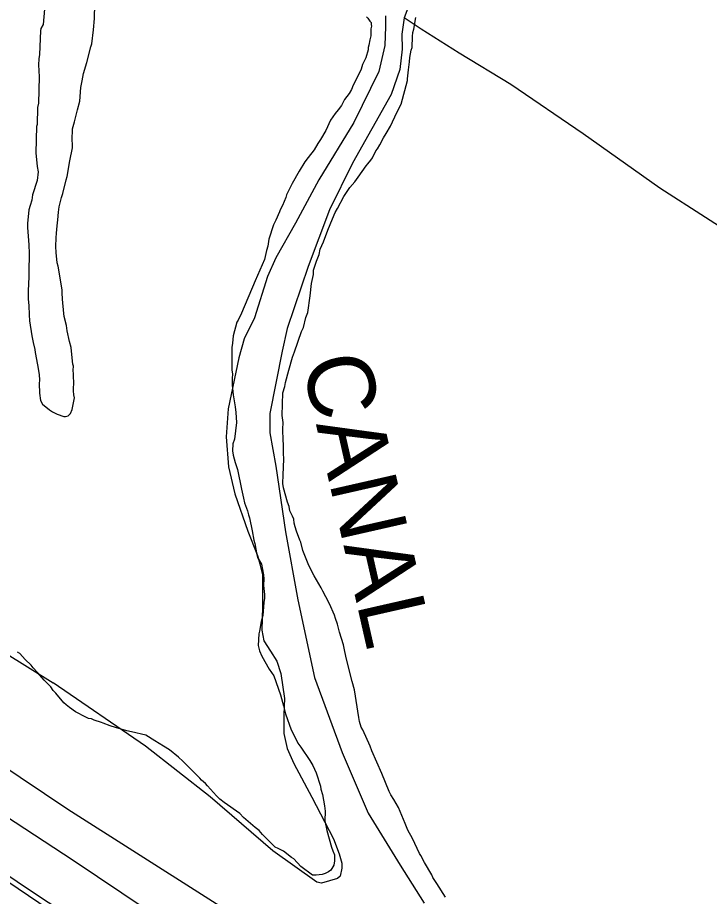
# Model space of a CAD drawing. Extents: x 3715084 to 3753216, y 488173 to 513963.
# Drawn here: x 3720247 to 3721106, y 496938 to 498029 of the extents above; entities that cross this region are included whole.
import ezdxf

# ---------------------------------------------------------------- set-up
doc = ezdxf.new("R2010")
doc.units = 0
for name, color, linetype in [('V-LEVE-TOET', 7, 'Continuous'), ('V-RIVR-IDEN', 7, 'Continuous'), ('V-SITE-VEGE', 7, 'Continuous'), ('V-TOPO-SHOR', 7, 'Continuous'), ('V-WETL-SWMP', 7, 'Continuous')]:
    doc.layers.add(name, color=color, linetype=linetype)

msp = doc.modelspace()

# ---------------------------------------------------------------- linework, layer by layer
at = {"layer": 'V-LEVE-TOET'}
for points in [[(3719301.4, 497645.3), (3719334, 497624.6), (3719454.3, 497539.9), (3719643.7, 497419.4), (3719836.8, 497295), (3719988.8, 497197.6), (3720147.5, 497093.2), (3720315.9, 496983.2)], [(3720181.6, 496999.6), (3720279.1, 496934.7), (3720444.1, 496828.8), (3720616.4, 496722.2)], [(3720315.9, 496983.2), (3720496, 496862.2), (3720657.3, 496764.2)]]:
    msp.add_lwpolyline(points, dxfattribs=at)
at = {"layer": 'V-SITE-VEGE'}
for p, q in [((3720283.9, 498079.1), (3720278.7, 498020.3)), ((3720342.4, 498027.6), (3720342.9, 498045.5)), ((3720341, 498013.5), (3720342.4, 498027.6)), ((3720680.1, 498029.8), (3720681.7, 498028.1)), ((3720681.7, 498028.1), (3720684.3, 498024.3)), ((3720739, 498014.5), (3720741.6, 498029.1)), ((3720275.8, 498015.1), (3720275.2, 498012.4)), ((3720278.7, 498020.3), (3720275.8, 498015.1)), ((3720684.3, 498024.3), (3720685.9, 498022.6)), ((3720685.7, 498015), (3720685.5, 498006.3)), ((3720686.3, 498018.2), (3720685.7, 498015)), ((3720685.9, 498022.6), (3720685.9, 498020.4)), ((3720685.9, 498020.4), (3720686.3, 498018.2)), ((3720275.2, 498012.4), (3720274.7, 497992.9)), ((3720338.9, 497996.1), (3720341, 498013.5)), ((3720685.5, 498006.3), (3720684.3, 498001.4)), ((3720736.8, 497991.7), (3720737.2, 498005.3)), ((3720737.2, 498005.3), (3720737.8, 498010.2)), ((3720737.8, 498010.2), (3720739, 498014.5)), ((3720337.7, 497992.4), (3720338.9, 497996.1)), ((3720683, 497994.4), (3720682.4, 497991.7)), ((3720684.3, 498001.4), (3720683, 497994.4)), ((3720273.9, 497982.6), (3720273.8, 497980.4)), ((3720274.7, 497992.9), (3720273.9, 497982.6)), ((3720332.9, 497972.9), (3720337.7, 497992.4)), ((3720682.3, 497989), (3720679.4, 497978.7)), ((3720682.4, 497991.7), (3720682.3, 497989)), ((3720733.8, 497979.3), (3720735.7, 497988.5)), ((3720735.7, 497988.5), (3720736.8, 497991.7)), ((3720273.2, 497977.7), (3720273, 497970.1)), ((3720273.8, 497980.4), (3720273.2, 497977.7)), ((3720328.7, 497959.4), (3720332.9, 497972.9)), ((3720679.4, 497978.7), (3720675.3, 497970.7)), ((3720732.3, 497964.1), (3720733.7, 497973.9)), ((3720733.7, 497973.9), (3720733.8, 497979.3)), ((3720273, 497970.1), (3720273.7, 497955.4)), ((3720672.4, 497962.1), (3720663.8, 497944.9)), ((3720673.6, 497964.7), (3720672.4, 497962.1)), ((3720675.3, 497970.7), (3720673.6, 497964.7)), ((3720730.9, 497952.7), (3720732.3, 497964.1)), ((3720273.7, 497955.4), (3720272.9, 497922.8)), ((3720325.6, 497942.1), (3720326.9, 497950.2)), ((3720326.9, 497950.2), (3720328.7, 497959.4)), ((3720723.1, 497921.4), (3720730.9, 497950.6)), ((3720730.9, 497950.6), (3720730.9, 497952.7)), ((3720324.1, 497925.3), (3720325.6, 497942.1)), ((3720661.5, 497939.5), (3720658.7, 497934.7)), ((3720663.8, 497944.9), (3720661.5, 497939.5)), ((3720658.7, 497934.7), (3720653, 497927.2)), ((3720271.7, 497917.4), (3720271.1, 497896.2)), ((3720272.9, 497922.8), (3720271.7, 497917.4)), ((3720321.1, 497914.5), (3720324.1, 497925.3)), ((3720649, 497919.7), (3720645.1, 497914.4)), ((3720653, 497927.2), (3720649, 497919.7)), ((3720717.9, 497911.2), (3720723.1, 497921.4)), ((3720317.4, 497899.4), (3720321.1, 497914.5)), ((3720638.4, 497905.8), (3720635.5, 497901.6)), ((3720641.2, 497909.6), (3720638.4, 497905.8)), ((3720645.1, 497914.4), (3720641.2, 497909.6)), ((3720709.9, 497894), (3720717.9, 497911.2)), ((3720271.1, 497896.2), (3720270.5, 497893.5)), ((3720315, 497890.7), (3720317.4, 497899.4)), ((3720635.5, 497901.6), (3720629.8, 497888.7)), ((3720270.5, 497893.5), (3720269.7, 497860.9)), ((3720314.7, 497876.6), (3720315, 497890.7)), ((3720629.8, 497888.7), (3720622.9, 497877.4)), ((3720701.3, 497879.5), (3720704.7, 497884.9)), ((3720704.7, 497884.9), (3720709.9, 497894)), ((3720315.1, 497871.7), (3720314.7, 497876.6)), ((3720622.9, 497877.4), (3720619.6, 497872.6)), ((3720696.8, 497871), (3720701.3, 497879.5)), ((3720311.8, 497851.1), (3720315, 497867.3)), ((3720315, 497867.3), (3720315.1, 497871.7)), ((3720615, 497864.6), (3720607.7, 497855)), ((3720619.6, 497872.6), (3720615, 497864.6)), ((3720687.7, 497854.9), (3720691.7, 497863.5)), ((3720691.7, 497863.5), (3720693.9, 497866.1)), ((3720693.9, 497866.1), (3720696.8, 497871)), ((3720269.7, 497860.9), (3720271.4, 497844)), ((3720308.6, 497831.6), (3720311.8, 497851.1)), ((3720607.7, 497855), (3720603.8, 497849.6)), ((3720682, 497847.4), (3720685.4, 497851.7)), ((3720685.4, 497851.7), (3720687.7, 497854.9)), ((3720271.4, 497844), (3720272.3, 497837.4)), ((3720603.8, 497849.6), (3720596.4, 497838.4)), ((3720669.7, 497830.9), (3720679.8, 497844.8)), ((3720679.8, 497844.8), (3720682, 497847.4)), ((3720272.3, 497837.4), (3720271, 497826.6)), ((3720307.4, 497827.3), (3720308.6, 497831.6)), ((3720596.4, 497838.4), (3720587.8, 497822.9)), ((3720665.7, 497825), (3720669.7, 497830.9)), ((3720271, 497826.6), (3720265.6, 497808.8)), ((3720303.2, 497810.6), (3720307.4, 497827.3)), ((3720587.8, 497822.9), (3720581, 497808.9)), ((3720659.5, 497818.1), (3720665.7, 497825)), ((3720265.6, 497808.8), (3720264.4, 497802.3)), ((3720301.4, 497805.7), (3720303.2, 497810.6)), ((3720581, 497808.9), (3720579.8, 497805.7)), ((3720652.2, 497806.9), (3720659.5, 497818.1)), ((3720264.4, 497802.3), (3720262.6, 497795.8)), ((3720298.4, 497793.8), (3720301.4, 497805.7)), ((3720579.8, 497805.7), (3720575.7, 497795.4)), ((3720644.2, 497791.8), (3720652.2, 497806.9)), ((3720260.8, 497790.4), (3720259.3, 497773.1)), ((3720262.6, 497795.8), (3720260.8, 497790.4)), ((3720296.9, 497777.6), (3720297.7, 497787.3)), ((3720297.7, 497787.3), (3720298.4, 497793.8)), ((3720572.3, 497787.9), (3720567.6, 497777.2)), ((3720572.9, 497790.1), (3720572.3, 497787.9)), ((3720575.7, 497795.4), (3720572.9, 497790.1)), ((3720637.9, 497779), (3720641.4, 497787)), ((3720641.4, 497787), (3720644.2, 497791.8)), ((3720296.2, 497770.5), (3720296.9, 497777.6)), ((3720567.6, 497777.2), (3720564.8, 497771.8)), ((3720632.1, 497765), (3720637.9, 497779)), ((3720259.3, 497773.1), (3720259.2, 497768.2)), ((3720259.2, 497768.2), (3720260.8, 497746.9)), ((3720295.4, 497761.3), (3720296.2, 497770.5)), ((3720564.8, 497771.8), (3720558.9, 497754)), ((3720626.8, 497750.4), (3720632.1, 497765)), ((3720294.4, 497744.5), (3720294.7, 497755.3)), ((3720294.7, 497755.3), (3720295.4, 497761.3)), ((3720558.9, 497754), (3720557.6, 497745.3)), ((3720260.8, 497746.9), (3720261.1, 497736.1)), ((3720294.8, 497737.4), (3720294.4, 497744.5)), ((3720557.6, 497745.3), (3720555.8, 497739.9)), ((3720622.8, 497741.3), (3720626.8, 497750.4)), ((3720261.1, 497736.1), (3720261, 497713.2)), ((3720296.1, 497724.3), (3720294.8, 497737.4)), ((3720555.8, 497739.9), (3720553.4, 497728.6)), ((3720618.1, 497726.7), (3720621.5, 497734.8)), ((3720621.5, 497734.8), (3720622.8, 497741.3)), ((3720297.1, 497720.5), (3720296.1, 497724.3)), ((3720302.3, 497691), (3720297.1, 497720.5)), ((3720553.4, 497728.6), (3720541.8, 497702.2)), ((3720614.5, 497715.4), (3720618.1, 497726.7)), ((3720261, 497713.2), (3720260.9, 497707.3)), ((3720611.9, 497698.6), (3720614.4, 497710)), ((3720614.4, 497710), (3720614.5, 497715.4)), ((3720260.9, 497707.3), (3720260.6, 497698)), ((3720541.8, 497702.2), (3720525, 497661.9)), ((3720610.4, 497683.4), (3720611.9, 497698.6)), ((3720260.6, 497698), (3720259.9, 497689.9)), ((3720259.9, 497689.9), (3720260.2, 497679.5)), ((3720302.2, 497687.2), (3720302.3, 497691)), ((3720260.2, 497679.5), (3720261, 497671.4)), ((3720302.6, 497679.5), (3720302.2, 497687.2)), ((3720304.3, 497661.6), (3720302.6, 497679.5)), ((3720607.2, 497662.8), (3720610.4, 497683.4)), ((3720261, 497671.4), (3720261.3, 497659.9)), ((3720261.3, 497659.9), (3720261.6, 497652.3)), ((3720304.7, 497657.7), (3720304.3, 497661.6)), ((3720307.7, 497646.8), (3720304.7, 497657.7)), ((3720525, 497661.9), (3720521, 497653.3)), ((3720601.8, 497644), (3720604.9, 497656.4)), ((3720604.9, 497656.4), (3720607.2, 497662.8)), ((3720261.6, 497652.3), (3720264.4, 497633.8)), ((3720308.6, 497640.2), (3720307.7, 497646.8)), ((3720519.3, 497650.6), (3720514.5, 497633.9)), ((3720521, 497653.3), (3720519.3, 497650.6)), ((3720599.5, 497639.1), (3720601.8, 497644)), ((3720264.4, 497633.8), (3720266.4, 497625.6)), ((3720311.5, 497626.6), (3720308.6, 497640.2)), ((3720514.5, 497633.9), (3720513.7, 497624.7)), ((3720590.7, 497613.8), (3720599.5, 497639.1)), ((3720266.4, 497625.6), (3720268.3, 497616.8)), ((3720313.5, 497619.5), (3720311.5, 497626.6)), ((3720513.7, 497624.7), (3720513.1, 497619.3)), ((3720268.3, 497616.8), (3720268.8, 497613)), ((3720268.8, 497613), (3720271.6, 497597.7)), ((3720313.9, 497614.6), (3720313.5, 497619.5)), ((3720315.7, 497598.7), (3720313.9, 497614.6)), ((3720513, 497616), (3720512.9, 497591.5)), ((3720513.1, 497619.3), (3720513, 497616)), ((3720588.4, 497607.3), (3720590.7, 497613.8)), ((3720583.6, 497591.1), (3720588.4, 497607.3)), ((3720271.6, 497597.7), (3720273.5, 497585.7)), ((3720316.2, 497596), (3720315.7, 497598.7)), ((3720316.1, 497591.1), (3720316.2, 497596)), ((3720316.5, 497586.2), (3720316.1, 497591.1)), ((3720512.9, 497591.5), (3720513.8, 497586.1)), ((3720579.4, 497576), (3720583.6, 497591.1)), ((3720273.5, 497585.7), (3720273.9, 497578.6)), ((3720273.9, 497578.6), (3720273.8, 497574.8)), ((3720316.4, 497581.3), (3720316.5, 497586.2)), ((3720316.8, 497578.1), (3720316.4, 497581.3)), ((3720513.8, 497586.1), (3720513.2, 497581.2)), ((3720513.2, 497581.2), (3720513.5, 497572.5)), ((3720273.8, 497574.8), (3720274, 497562.8)), ((3720316.5, 497565.6), (3720316.8, 497578.1)), ((3720513.5, 497572.5), (3720514.8, 497560.5)), ((3720576.4, 497563.1), (3720578.8, 497571.1)), ((3720578.8, 497571.1), (3720579.4, 497576)), ((3720274, 497562.8), (3720275.4, 497553.6)), ((3720314.8, 497542.2), (3720317.4, 497556.8)), ((3720316.9, 497560.7), (3720316.5, 497565.6)), ((3720317.4, 497556.8), (3720316.9, 497560.7)), ((3720514.8, 497560.5), (3720517.2, 497545.8)), ((3720575.6, 497534.8), (3720576.4, 497563.1)), ((3720275.4, 497553.6), (3720278, 497549.1)), ((3720278, 497549.1), (3720286.5, 497541.9)), ((3720517.2, 497545.8), (3720518.1, 497538.7)), ((3720286.5, 497541.9), (3720290.3, 497539.6)), ((3720290.3, 497539.6), (3720296.2, 497536.7)), ((3720296.2, 497536.7), (3720304.3, 497533.8)), ((3720309.7, 497534.7), (3720312.5, 497537.4)), ((3720312.5, 497537.4), (3720314.8, 497542.2)), ((3720518.1, 497538.7), (3720518.8, 497526.1)), ((3720576.5, 497526.1), (3720575.6, 497534.8)), ((3720304.3, 497533.8), (3720306.4, 497533.7)), ((3720306.4, 497533.7), (3720309.7, 497534.7)), ((3720518.8, 497526.1), (3720516.1, 497505.6)), ((3720576.3, 497517.9), (3720576.5, 497526.1)), ((3720576.5, 497503.8), (3720576.3, 497517.9)), ((3720516.1, 497505.6), (3720514.3, 497499.6)), ((3720576.9, 497499.4), (3720576.5, 497503.8)), ((3720514.3, 497499.6), (3720513.6, 497490.9)), ((3720577.2, 497488), (3720576.9, 497499.4)), ((3720513.6, 497490.9), (3720514.5, 497485.5)), ((3720514.5, 497485.5), (3720517, 497476.7)), ((3720576.5, 497461.4), (3720577.5, 497480.9)), ((3720577.5, 497480.9), (3720577.2, 497488)), ((3720517, 497476.7), (3720520.1, 497467.9)), ((3720520.1, 497467.9), (3720524.9, 497443.3)), ((3720576.2, 497450.5), (3720576.5, 497461.4)), ((3720577.2, 497445.1), (3720576.2, 497450.5)), ((3720524.9, 497443.3), (3720527.3, 497432.4)), ((3720582.1, 497427.5), (3720577.2, 497445.1)), ((3720527.3, 497432.4), (3720528.8, 497426.4)), ((3720528.8, 497426.4), (3720532.3, 497416.5)), ((3720584.2, 497422), (3720582.1, 497427.5)), ((3720532.3, 497416.5), (3720533.8, 497411.6)), ((3720585.1, 497416.6), (3720584.2, 497422)), ((3720588.2, 497410), (3720585.1, 497416.6)), ((3720533.8, 497411.6), (3720534.8, 497407.8)), ((3720534.8, 497407.8), (3720538.2, 497391.9)), ((3720589.8, 497406.1), (3720588.2, 497410)), ((3720590.2, 497401.2), (3720589.8, 497406.1)), ((3720591.7, 497396.8), (3720590.2, 497401.2)), ((3720593.2, 497391.4), (3720591.7, 497396.8)), ((3720538.2, 497391.9), (3720540.1, 497380.4)), ((3720594.7, 497387), (3720593.2, 497391.4)), ((3720595.7, 497384.8), (3720594.7, 497387)), ((3720597.3, 497380.4), (3720595.7, 497384.8)), ((3720540.1, 497380.4), (3720541.6, 497376)), ((3720541.6, 497376), (3720544, 497361.9)), ((3720598.8, 497377.6), (3720597.3, 497380.4)), ((3720601.3, 497367.2), (3720598.8, 497377.6)), ((3720544, 497361.9), (3720545, 497358.6)), ((3720608.4, 497348.6), (3720601.3, 497367.2)), ((3720545, 497358.6), (3720549.7, 497350.3)), ((3720549.7, 497350.3), (3720552.1, 497337.2)), ((3720615.1, 497335.9), (3720608.4, 497348.6)), ((3720552.1, 497337.2), (3720552.5, 497332.3)), ((3720552.5, 497332.3), (3720552.3, 497324.1)), ((3720624, 497321), (3720615.1, 497335.9)), ((3720552.3, 497324.1), (3720553.6, 497312.7)), ((3720626.1, 497317.1), (3720624, 497321)), ((3720629.7, 497310), (3720626.1, 497317.1)), ((3720553.5, 497308.3), (3720552.8, 497302.9)), ((3720553.6, 497312.7), (3720553.5, 497308.3)), ((3720634.4, 497301.1), (3720629.7, 497310)), ((3720552.8, 497302.9), (3720551.3, 497286.6)), ((3720640.5, 497286.9), (3720634.4, 497301.1)), ((3720551.3, 497286.6), (3720549.5, 497279.1)), ((3720641.5, 497283), (3720640.5, 497286.9)), ((3720549.5, 497279.1), (3720547.5, 497267.2)), ((3720644.1, 497275.9), (3720641.5, 497283)), ((3720646.5, 497266), (3720644.1, 497275.9)), ((3720546.4, 497263.9), (3720545.5, 497249.3)), ((3720547.5, 497267.2), (3720546.4, 497263.9)), ((3720651.6, 497250.1), (3720646.5, 497266)), ((3720249.5, 497239.4), (3720246.8, 497241.1)), ((3720545.5, 497249.3), (3720547.5, 497242.7)), ((3720547.5, 497242.7), (3720550, 497236.1)), ((3720652.5, 497246.3), (3720651.6, 497250.1)), ((3720655, 497234.3), (3720652.5, 497246.3)), ((3720256.3, 497232.2), (3720249.5, 497239.4)), ((3720263.8, 497224.9), (3720256.3, 497232.2)), ((3720550, 497236.1), (3720559.4, 497220.1)), ((3720662.4, 497204.7), (3720655, 497234.3)), ((3720266.4, 497221.6), (3720263.8, 497224.9)), ((3720271.7, 497216), (3720266.4, 497221.6)), ((3720559.4, 497220.1), (3720565.2, 497211.8)), ((3720280.1, 497206.6), (3720271.7, 497216)), ((3720565.2, 497211.8), (3720573.3, 497188.2)), ((3720288.1, 497198.2), (3720280.1, 497206.6)), ((3720291.2, 497193.8), (3720288.1, 497198.2)), ((3720665.4, 497194.3), (3720662.4, 497204.7)), ((3720294.4, 497190.4), (3720291.2, 497193.8)), ((3720304.4, 497178.2), (3720294.4, 497190.4)), ((3720573.3, 497188.2), (3720577.3, 497174.5)), ((3720670.5, 497160), (3720665.4, 497194.3)), ((3720307.1, 497176), (3720304.4, 497178.2)), ((3720311.4, 497172.6), (3720307.1, 497176)), ((3720318.8, 497167), (3720311.4, 497172.6)), ((3720331.7, 497160.7), (3720318.8, 497167)), ((3720577.3, 497174.5), (3720579.7, 497164.7)), ((3720579.7, 497164.7), (3720586.8, 497144.9)), ((3720334.9, 497159), (3720331.7, 497160.7)), ((3720338.7, 497158.3), (3720334.9, 497159)), ((3720341.9, 497156.6), (3720338.7, 497158.3)), ((3720351.1, 497153.7), (3720341.9, 497156.6)), ((3720353.3, 497153.1), (3720351.1, 497153.7)), ((3720361.9, 497149.6), (3720353.3, 497153.1)), ((3720671.4, 497155), (3720670.5, 497160)), ((3720673.4, 497147.9), (3720671.4, 497155)), ((3720368.3, 497147.8), (3720361.9, 497149.6)), ((3720382.4, 497143.6), (3720368.3, 497147.8)), ((3720388.3, 497142.4), (3720382.4, 497143.6)), ((3720406.2, 497138.1), (3720388.3, 497142.4)), ((3720586.8, 497144.9), (3720592, 497134.5)), ((3720675.5, 497144.6), (3720673.4, 497147.9)), ((3720684.8, 497124.3), (3720675.5, 497144.6)), ((3720417.4, 497131.3), (3720406.2, 497138.1)), ((3720428.1, 497124.5), (3720417.4, 497131.3)), ((3720592, 497134.5), (3720595.1, 497128.4)), ((3720435.6, 497120), (3720428.1, 497124.5)), ((3720595.1, 497128.4), (3720598.8, 497123.4)), ((3720598.8, 497123.4), (3720609.8, 497106.8)), ((3720686.8, 497118.8), (3720684.8, 497124.3)), ((3720446.8, 497111), (3720435.6, 497120)), ((3720452.1, 497106), (3720446.8, 497111)), ((3720699.1, 497090.7), (3720686.8, 497118.8)), ((3720457.4, 497100.4), (3720452.1, 497106)), ((3720463.2, 497094.8), (3720457.4, 497100.4)), ((3720609.8, 497106.8), (3720613.4, 497100.7)), ((3720613.4, 497100.7), (3720617.5, 497091.4)), ((3720473.3, 497084.8), (3720463.2, 497094.8)), ((3720617.5, 497091.4), (3720623.1, 497074.9)), ((3720708.3, 497068.2), (3720699.1, 497090.7)), ((3720475.4, 497082.5), (3720473.3, 497084.8)), ((3720480.2, 497078.1), (3720475.4, 497082.5)), ((3720482.8, 497075.3), (3720480.2, 497078.1)), ((3720493.9, 497063), (3720482.8, 497075.3)), ((3720623.1, 497074.9), (3720623.6, 497071.1)), ((3720623.6, 497071.1), (3720625.6, 497064.6)), ((3720710.4, 497064.3), (3720708.3, 497068.2)), ((3720498.2, 497058.6), (3720493.9, 497063)), ((3720503.5, 497054.6), (3720498.2, 497058.6)), ((3720625.6, 497064.6), (3720627.9, 497050.4)), ((3720714.1, 497058.3), (3720710.4, 497064.3)), ((3720719.8, 497048.3), (3720714.1, 497058.3)), ((3720522.7, 497041.1), (3720503.5, 497054.6)), ((3720627.9, 497050.4), (3720628.8, 497043.8)), ((3720728, 497028.5), (3720719.8, 497048.3)), ((3720527.5, 497036.1), (3720522.7, 497041.1)), ((3720541.9, 497023.7), (3720527.5, 497036.1)), ((3720628.8, 497043.8), (3720628.5, 497031.9)), ((3720546.7, 497019.8), (3720541.9, 497023.7)), ((3720628.5, 497031.9), (3720630.9, 497019.8)), ((3720731.6, 497020.3), (3720728, 497028.5)), ((3720550.9, 497014.8), (3720546.7, 497019.8)), ((3720565.2, 497000.9), (3720550.9, 497014.8)), ((3720630.9, 497019.8), (3720636.9, 496999)), ((3720737.3, 497009.8), (3720731.6, 497020.3)), ((3720566.8, 496999.2), (3720565.2, 497000.9)), ((3720746.1, 496991.1), (3720737.3, 497009.8)), ((3720570.6, 496997.5), (3720566.8, 496999.2)), ((3720577, 496994), (3720570.6, 496997.5)), ((3720587.1, 496986.2), (3720577, 496994)), ((3720636.9, 496999), (3720638.4, 496994.6)), ((3720638.4, 496994.6), (3720640.5, 496989.7)), ((3720640.5, 496989.7), (3720640.3, 496982.1)), ((3720747.6, 496988.9), (3720746.1, 496991.1)), ((3720589.8, 496984.5), (3720587.1, 496986.2)), ((3720598.8, 496975), (3720589.8, 496984.5)), ((3720640.3, 496982.1), (3720639.6, 496976.7)), ((3720752.3, 496980.1), (3720747.6, 496988.9)), ((3720761.2, 496964.6), (3720752.3, 496980.1)), ((3720613.2, 496964.3), (3720598.8, 496975)), ((3720632.9, 496968.7), (3720629, 496966.6)), ((3720635.7, 496970.8), (3720632.9, 496968.7)), ((3720639.6, 496976.7), (3720635.7, 496970.8)), ((3720617.6, 496964.2), (3720613.2, 496964.3)), ((3720625.2, 496965.1), (3720617.6, 496964.2)), ((3720629, 496966.6), (3720625.2, 496965.1)), ((3720762.7, 496961.3), (3720761.2, 496964.6)), ((3720767.4, 496954.1), (3720762.7, 496961.3)), ((3720778.4, 496937), (3720767.4, 496954.1))]:
    msp.add_line(p, q, dxfattribs=at)
at = {"layer": 'V-TOPO-SHOR'}
for points in [[(3720731.4, 498040.4), (3720727.1, 498028.6), (3720723.9, 498008.2), (3720724.3, 497989.7), (3720721.6, 497964.4), (3720710.9, 497933.5), (3720662.9, 497848.3), (3720634.2, 497790.4), (3720607.6, 497720), (3720581.6, 497642.8), (3720575.3, 497614.7), (3720560.1, 497537.3), (3720560.1, 497513.4), (3720567.7, 497472), (3720579.6, 497390.6), (3720594.7, 497306), (3720615.5, 497209.9), (3720649.8, 497116.7), (3720682.4, 497041.5), (3720721.9, 496976.9), (3720751.7, 496929.6)], [(3720703.9, 498031.1), (3720703.7, 498017.6), (3720702.8, 497994.1), (3720695.3, 497961.9), (3720664.4, 497898.7), (3720621.1, 497827.4), (3720591.9, 497773.7), (3720567.5, 497730.8), (3720557.1, 497707.6), (3720540.9, 497656.3), (3720528.4, 497629.9), (3720521.6, 497606.7), (3720508.4, 497543.3), (3720505.9, 497508.5), (3720508.8, 497471.2), (3720516.7, 497437.9), (3720532.9, 497391.3), (3720544.8, 497361.3), (3720547.7, 497351), (3720551.1, 497337.1), (3720550.9, 497297.4), (3720550.1, 497268.5), (3720552.6, 497255.4), (3720561, 497242.5), (3720568.9, 497230), (3720573.7, 497214.8), (3720578.4, 497183.7), (3720577.4, 497163.9), (3720577.4, 497140.4), (3720581.8, 497121.6), (3720589.9, 497102.8), (3720612.3, 497061.2), (3720639, 497009.4), (3720646.1, 496991), (3720649.5, 496979.4), (3720649.6, 496973.1), (3720647.6, 496963.1), (3720644, 496960.3), (3720624.3, 496954.5)], [(3721551.9, 497492.6), (3721515.4, 497517.8), (3721419.9, 497576.5), (3721313.9, 497646.2), (3721157.8, 497744.3), (3721044.5, 497817), (3720949.4, 497884.7), (3720859.3, 497945.7), (3720795.4, 497984.6), (3720747.9, 498014.4), (3720727.1, 498028.6)], [(3719299, 497841.7), (3719314.1, 497831.6), (3719570.8, 497671.6), (3719695.9, 497591.9), (3719793, 497530), (3720083.9, 497343), (3720126.8, 497307.7), (3720166.6, 497280.4), (3720291.1, 497203.3)], [(3719300.5, 497714), (3719567.4, 497540), (3719895.8, 497323.4), (3720309.3, 497046.5)], [(3720624.3, 496954.5), (3720618.4, 496955.8), (3720563.9, 496994.4), (3720486, 497061.5), (3720405.8, 497124.5), (3720291.1, 497203.3)], [(3720309.3, 497046.5), (3720479.8, 496937.8), (3720638.2, 496837.1), (3720771.1, 496756.1), (3720924.1, 496655.3), (3721002.1, 496612.6)]]:
    msp.add_lwpolyline(points, dxfattribs=at)
at = {"layer": 'V-WETL-SWMP'}
msp.add_line((3720350.8, 496877.9), (3719813.8, 497239.8), dxfattribs=at)

# ---------------------------------------------------------------- texts
at = {"layer": 'V-RIVR-IDEN'}
msp.add_text('CANAL', height=83, rotation=282.8043, dxfattribs=at).set_placement((3720599.5, 497602.5))

doc.saveas('drawing.dxf')
